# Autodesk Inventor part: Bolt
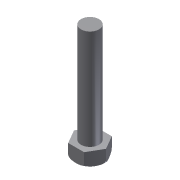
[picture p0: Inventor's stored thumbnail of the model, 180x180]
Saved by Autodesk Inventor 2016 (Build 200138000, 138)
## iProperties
Shininess: 77.0
Length Units: 11269
Angle Units: 11279
Time Units: 11290
Mass Units: 11283
Length Display Precision: 3
Angle Display Precision: 2
Created: 2002-02
Part Number: Bolt
Document SubType Name: Modeling
Designer: ***
Density: 1 g/cm^3
Material: Generic
Appearance: Default
Density: 0.0
Volumn: 0.0
Area: 0.0
PropertySet Name: Model Information
Control State: 0
Master: False
Checked Out: False
Author: ***
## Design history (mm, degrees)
sketch "Sketch1"
  geometry: C1 r 4 at (0, 0)
  constraints: 1 centre point
  dimensions: "d0" = 8 diameter of C1
extrude "Extrusion1" new body sketch "Sketch1" stored distance "d1" = 3.5; taper "d2" = 0 deg
fillet "Fillet1" dims "d3" = 1
sketch "Sketch2"
  geometry: L1 (4, 0)-(2, -3.464); L2 (2, -3.464)-(-2, -3.464); L3 (-2, -3.464)-(-4, 0); L4 (-4, 0)-(-2, 3.464); L5 (-2, 3.464)-(2, 3.464); L6 (2, 3.464)-(4, 0); 2 further points
  constraints: 12 end point, 1 coincident, 11 other
extrude "Extrusion2" sketch "Sketch2" stored distance "d4" = 3.5; taper "d5" = 0 deg
sketch "Sketch3"
  geometry: C1 r 2.25 at (0, 0)
  constraints: 1 centre point
  dimensions: "d6" = 4.5 diameter of C1
extrude "Extrusion3" join sketch "Sketch3" distance "d7" = 25; taper "d8" = 0 deg
body "Solid1"
